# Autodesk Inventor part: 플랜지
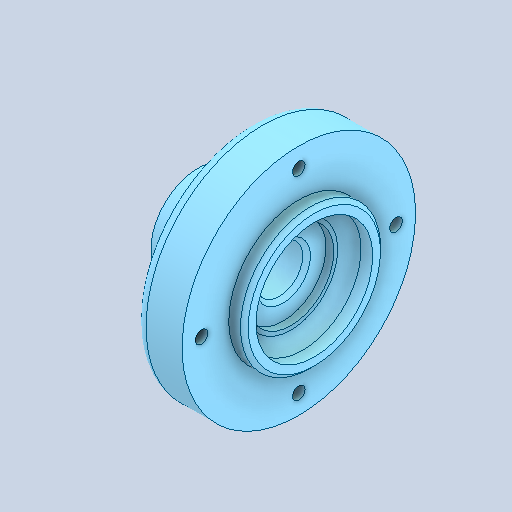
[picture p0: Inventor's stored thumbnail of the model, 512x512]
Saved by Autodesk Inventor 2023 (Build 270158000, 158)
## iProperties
Created: 2026-03
Part Number: 플랜지
Material: 강철, 연강
Document SubType Name: Modeling
Designer: 4강의실
Density: 7.85 g/cm^3
Appearance: 기본값
Author: jhkim
Sending System: Autodesk Inventor 2026
Preprocessor: ST-DEVELOPER v20.1
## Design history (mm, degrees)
feature "솔리드1"
node "솔리드2"
